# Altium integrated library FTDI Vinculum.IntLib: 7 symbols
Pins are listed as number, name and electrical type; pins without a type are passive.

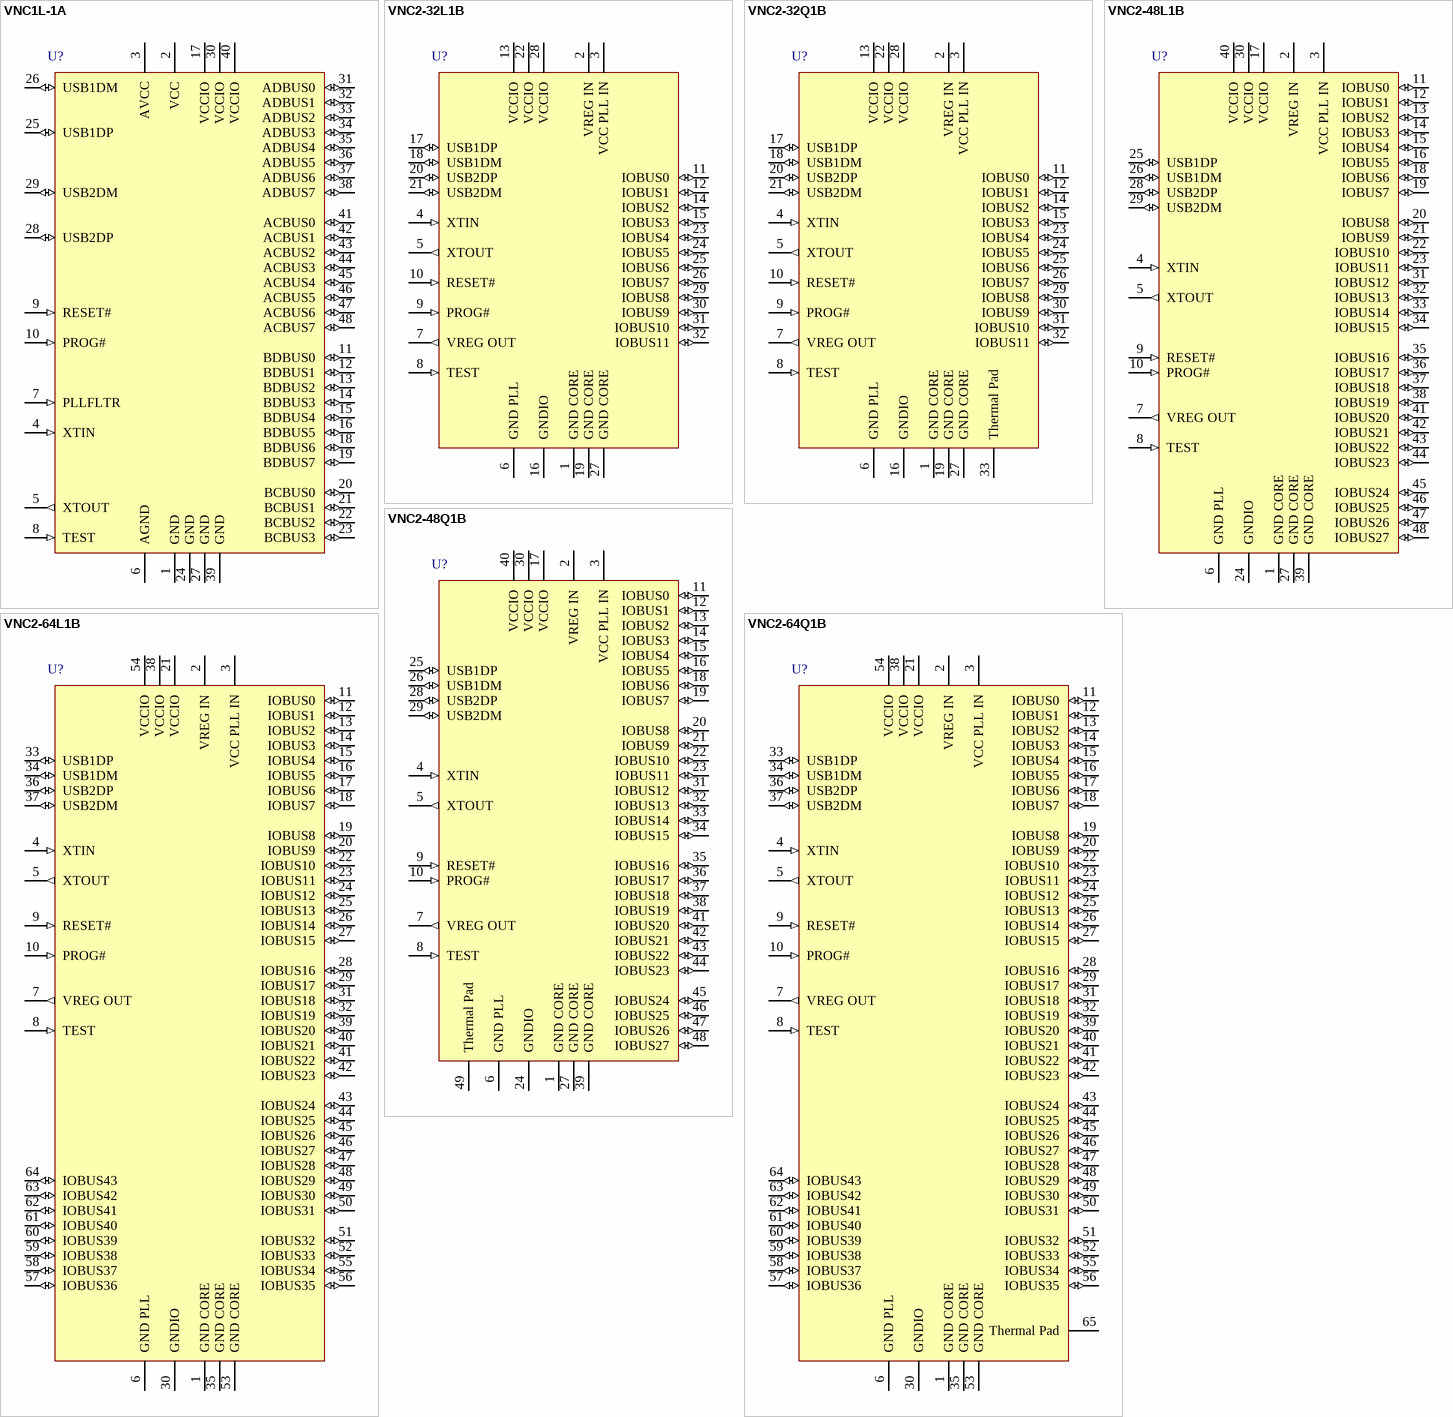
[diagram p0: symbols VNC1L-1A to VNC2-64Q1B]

## VNC1L-1A
designator U?
Vinculum Embedded USB Host Controller Chip, 48-pin LQFP; Manufacturer: FTDI; PartNumber: VNC1L-1A
footprint LQFP-48_N (Thin QFP, 48-Leads, Body 7x7mm, Pitch 0.5mm, IPC Medium Density)
footprint LQFP-48_L (Thin QFP, 48-Leads, Body 7x7mm, Pitch 0.5mm, IPC High Density)
footprint LQFP-48_M (Thin QFP, 48-Leads, Body 7x7mm, Pitch 0.5mm, IPC Low Density)
pins: 1 GND (power), 2 VCC (power), 3 AVCC (power), 4 XTIN (in), 5 XTOUT (out), 6 AGND (power), 7 PLLFLTR (in), 8 TEST (in), 9 RESET# (in), 10 PROG# (in), 11 BDBUS0 (io), 12 BDBUS1 (io), 13 BDBUS2 (io), 14 BDBUS3 (io), 15 BDBUS4 (io), 16 BDBUS5 (io), 17 VCCIO (power), 18 BDBUS6 (io), 19 BDBUS7 (io), 20 BCBUS0 (io), 21 BCBUS1 (io), 22 BCBUS2 (io), 23 BCBUS3 (io), 24 GND (power), 25 USB1DP (io), 26 USB1DM (io), 27 GND (power), 28 USB2DP (io), 29 USB2DM (io), 30 VCCIO (power), 31 ADBUS0 (io), 32 ADBUS1 (io), 33 ADBUS2 (io), 34 ADBUS3 (io), 35 ADBUS4 (io), 36 ADBUS5 (io), 37 ADBUS6 (io), 38 ADBUS7 (io), 39 GND (power), 40 VCCIO (power), 41 ACBUS0 (io), 42 ACBUS1 (io), 43 ACBUS2 (io), 44 ACBUS3 (io), 45 ACBUS4 (io), 46 ACBUS5 (io), 47 ACBUS6 (io), 48 ACBUS7 (io)

## VNC2-32L1B
designator U?
Vinculum-II Embedded Dual USB Host Controller Chip, 32-pin LQFP; Manufacturer: FTDI; PartNumber: VNC2-32L1B
footprint LQFP-32_N (Thin QFP, 32-Leads, Body 7x7mm, Pitch 0.8mm, IPC Medium Density)
footprint LQFP-32_L (Thin QFP, 32-Leads, Body 7x7mm, Pitch 0.8mm, IPC High Density)
footprint LQFP-32_M (Thin QFP, 32-Leads, Body 7x7mm, Pitch 0.8mm, IPC Low Density)
pins: 1 GND CORE (power), 2 VREG IN (power), 3 VCC PLL IN (power), 4 XTIN (in), 5 XTOUT (out), 6 GND PLL (power), 7 VREG OUT (out), 8 TEST (in), 9 PROG# (in), 10 RESET# (in), 11 IOBUS0 (io), 12 IOBUS1 (io), 13 VCCIO (power), 14 IOBUS2 (io), 15 IOBUS3 (io), 16 GNDIO (power), 17 USB1DP (io), 18 USB1DM (io), 19 GND CORE (power), 20 USB2DP (io), 21 USB2DM (io), 22 VCCIO (power), 23 IOBUS4 (io), 24 IOBUS5 (io), 25 IOBUS6 (io), 26 IOBUS7 (io), 27 GND CORE (power), 28 VCCIO (power), 29 IOBUS8 (io), 30 IOBUS9 (io), 31 IOBUS10 (io), 32 IOBUS11 (io)

## VNC2-32Q1B
designator U?
Vinculum-II Embedded Dual USB Host Controller Chip, 32-pin QFN; Manufacturer: FTDI; PartNumber: VNC2-32Q1B
footprint QFN7X7-32_N (QFN, 32-Leads, Body 7x7mm, Pitch 0.65mm, Thermal Pad 4.8x4.8mm, IPC Medium Density)
footprint QFN7X7-32_L (QFN, 32-Leads, Body 7x7mm, Pitch 0.65mm, Thermal Pad 4.8x4.8mm, IPC High Density)
footprint QFN7X7-32_M (QFN, 32-Leads, Body 7x7mm, Pitch 0.65mm, Thermal Pad 4.8x4.8mm, IPC Low Density)
pins: 1 GND CORE (power), 2 VREG IN (power), 3 VCC PLL IN (power), 4 XTIN (in), 5 XTOUT (out), 6 GND PLL (power), 7 VREG OUT (out), 8 TEST (in), 9 PROG# (in), 10 RESET# (in), 11 IOBUS0 (io), 12 IOBUS1 (io), 13 VCCIO (power), 14 IOBUS2 (io), 15 IOBUS3 (io), 16 GNDIO (power), 17 USB1DP (io), 18 USB1DM (io), 19 GND CORE (power), 20 USB2DP (io), 21 USB2DM (io), 22 VCCIO (power), 23 IOBUS4 (io), 24 IOBUS5 (io), 25 IOBUS6 (io), 26 IOBUS7 (io), 27 GND CORE (power), 28 VCCIO (power), 29 IOBUS8 (io), 30 IOBUS9 (io), 31 IOBUS10 (io), 32 IOBUS11 (io), 33 Thermal Pad

## VNC2-48L1B
designator U?
Vinculum-II Embedded Dual USB Host Controller Chip, 48-pin LQFP; Manufacturer: FTDI; PartNumber: VNC2-48L1B
footprint LQFP-48_N (Thin QFP, 48-Leads, Body 7x7mm, Pitch 0.5mm, IPC Medium Density)
footprint LQFP-48_L (Thin QFP, 48-Leads, Body 7x7mm, Pitch 0.5mm, IPC High Density)
footprint LQFP-48_M (Thin QFP, 48-Leads, Body 7x7mm, Pitch 0.5mm, IPC Low Density)
pins: 1 GND CORE (power), 2 VREG IN (power), 3 VCC PLL IN (power), 4 XTIN (in), 5 XTOUT (out), 6 GND PLL (power), 7 VREG OUT (out), 8 TEST (in), 9 RESET# (in), 10 PROG# (in), 11 IOBUS0 (io), 12 IOBUS1 (io), 13 IOBUS2 (io), 14 IOBUS3 (io), 15 IOBUS4 (io), 16 IOBUS5 (io), 17 VCCIO (power), 18 IOBUS6 (io), 19 IOBUS7 (io), 20 IOBUS8 (io), 21 IOBUS9 (io), 22 IOBUS10 (io), 23 IOBUS11 (io), 24 GNDIO (power), 25 USB1DP (io), 26 USB1DM (io), 27 GND CORE (power), 28 USB2DP (io), 29 USB2DM (io), 30 VCCIO (power), 31 IOBUS12 (io), 32 IOBUS13 (io), 33 IOBUS14 (io), 34 IOBUS15 (io), 35 IOBUS16 (io), 36 IOBUS17 (io), 37 IOBUS18 (io), 38 IOBUS19 (io), 39 GND CORE (power), 40 VCCIO (power), 41 IOBUS20 (io), 42 IOBUS21 (io), 43 IOBUS22 (io), 44 IOBUS23 (io), 45 IOBUS24 (io), 46 IOBUS25 (io), 47 IOBUS26 (io), 48 IOBUS27 (io)

## VNC2-48Q1B
designator U?
Vinculum-II Embedded Dual USB Host Controller Chip, 48-pin QFN; Manufacturer: FTDI; PartNumber: VNC2-48Q1B
footprint QFN48_N (QFN, 48-Leads, Body 8x8mm, Pitch 0.5mm, Thermal Pad 6.3x6.3mm, IPC Medium Density)
footprint QFN48_L (QFN, 48-Leads, Body 8x8mm, Pitch 0.5mm, Thermal Pad 6.3x6.3mm, IPC High Density)
footprint QFN48_M (QFN, 48-Leads, Body 8x8mm, Pitch 0.5mm, Thermal Pad 6.3x6.3mm, IPC Low Density)
pins: 1 GND CORE (power), 2 VREG IN (power), 3 VCC PLL IN (power), 4 XTIN (in), 5 XTOUT (out), 6 GND PLL (power), 7 VREG OUT (out), 8 TEST (in), 9 RESET# (in), 10 PROG# (in), 11 IOBUS0 (io), 12 IOBUS1 (io), 13 IOBUS2 (io), 14 IOBUS3 (io), 15 IOBUS4 (io), 16 IOBUS5 (io), 17 VCCIO (power), 18 IOBUS6 (io), 19 IOBUS7 (io), 20 IOBUS8 (io), 21 IOBUS9 (io), 22 IOBUS10 (io), 23 IOBUS11 (io), 24 GNDIO (power), 25 USB1DP (io), 26 USB1DM (io), 27 GND CORE (power), 28 USB2DP (io), 29 USB2DM (io), 30 VCCIO (power), 31 IOBUS12 (io), 32 IOBUS13 (io), 33 IOBUS14 (io), 34 IOBUS15 (io), 35 IOBUS16 (io), 36 IOBUS17 (io), 37 IOBUS18 (io), 38 IOBUS19 (io), 39 GND CORE (power), 40 VCCIO (power), 41 IOBUS20 (io), 42 IOBUS21 (io), 43 IOBUS22 (io), 44 IOBUS23 (io), 45 IOBUS24 (io), 46 IOBUS25 (io), 47 IOBUS26 (io), 48 IOBUS27 (io), 49 Thermal Pad

## VNC2-64L1B
designator U?
Vinculum-II Embedded Dual USB Host Controller Chip, 64-pin LQFP; Manufacturer: FTDI; PartNumber: VNC2-64L1B
footprint LQFP-64_N (Thin QFP, 64-Leads, Body 10x10mm, Pitch 0.5mm, IPC Medium Density)
footprint LQFP-64_L (Thin QFP, 64-Leads, Body 10x10mm, Pitch 0.5mm, IPC High Density)
footprint LQFP-64_M (Thin QFP, 64-Leads, Body 10x10mm, Pitch 0.5mm, IPC Low Density)
pins: 1 GND CORE (power), 2 VREG IN (power), 3 VCC PLL IN (power), 4 XTIN (in), 5 XTOUT (out), 6 GND PLL (power), 7 VREG OUT (out), 8 TEST (in), 9 RESET# (in), 10 PROG# (in), 11 IOBUS0 (io), 12 IOBUS1 (io), 13 IOBUS2 (io), 14 IOBUS3 (io), 15 IOBUS4 (io), 16 IOBUS5 (io), 17 IOBUS6 (io), 18 IOBUS7 (io), 19 IOBUS8 (io), 20 IOBUS9 (io), 21 VCCIO (power), 22 IOBUS10 (io), 23 IOBUS11 (io), 24 IOBUS12 (io), 25 IOBUS13 (io), 26 IOBUS14 (io), 27 IOBUS15 (io), 28 IOBUS16 (io), 29 IOBUS17 (io), 30 GNDIO (power), 31 IOBUS18 (io), 32 IOBUS19 (io), 33 USB1DP (io), 34 USB1DM (io), 35 GND CORE (power), 36 USB2DP (io), 37 USB2DM (io), 38 VCCIO (power), 39 IOBUS20 (io), 40 IOBUS21 (io), 41 IOBUS22 (io), 42 IOBUS23 (io), 43 IOBUS24 (io), 44 IOBUS25 (io), 45 IOBUS26 (io), 46 IOBUS27 (io), 47 IOBUS28 (io), 48 IOBUS29 (io), 49 IOBUS30 (io), 50 IOBUS31 (io), 51 IOBUS32 (io), 52 IOBUS33 (io), 53 GND CORE (power), 54 VCCIO (power), 55 IOBUS34 (io), 56 IOBUS35 (io), 57 IOBUS36 (io), 58 IOBUS37 (io), 59 IOBUS38 (io), 60 IOBUS39 (io), 61 IOBUS40 (io), 62 IOBUS41 (io), 63 IOBUS42 (io), 64 IOBUS43 (io)

## VNC2-64Q1B
designator U?
Vinculum-II Embedded Dual USB Host Controller Chip, 64-pin QFN; Manufacturer: FTDI; PartNumber: VNC2-64Q1B
footprint QFN64_N (QFN, 64-Leads, Body 8x8mm, Pitch 0.4mm, Thermal Pad 6.3x6.3mm, IPC Medium Density)
footprint QFN64_L (QFN, 64-Leads, Body 8x8mm, Pitch 0.4mm, Thermal Pad 6.3x6.3mm, IPC High Density)
footprint QFN64_M (QFN, 64-Leads, Body 8x8mm, Pitch 0.4mm, Thermal Pad 6.3x6.3mm, IPC Low Density)
pins: 1 GND CORE (power), 2 VREG IN (power), 3 VCC PLL IN (power), 4 XTIN (in), 5 XTOUT (out), 6 GND PLL (power), 7 VREG OUT (out), 8 TEST (in), 9 RESET# (in), 10 PROG# (in), 11 IOBUS0 (io), 12 IOBUS1 (io), 13 IOBUS2 (io), 14 IOBUS3 (io), 15 IOBUS4 (io), 16 IOBUS5 (io), 17 IOBUS6 (io), 18 IOBUS7 (io), 19 IOBUS8 (io), 20 IOBUS9 (io), 21 VCCIO (power), 22 IOBUS10 (io), 23 IOBUS11 (io), 24 IOBUS12 (io), 25 IOBUS13 (io), 26 IOBUS14 (io), 27 IOBUS15 (io), 28 IOBUS16 (io), 29 IOBUS17 (io), 30 GNDIO (power), 31 IOBUS18 (io), 32 IOBUS19 (io), 33 USB1DP (io), 34 USB1DM (io), 35 GND CORE (power), 36 USB2DP (io), 37 USB2DM (io), 38 VCCIO (power), 39 IOBUS20 (io), 40 IOBUS21 (io), 41 IOBUS22 (io), 42 IOBUS23 (io), 43 IOBUS24 (io), 44 IOBUS25 (io), 45 IOBUS26 (io), 46 IOBUS27 (io), 47 IOBUS28 (io), 48 IOBUS29 (io), 49 IOBUS30 (io), 50 IOBUS31 (io), 51 IOBUS32 (io), 52 IOBUS33 (io), 53 GND CORE (power), 54 VCCIO (power), 55 IOBUS34 (io), 56 IOBUS35 (io), 57 IOBUS36 (io), 58 IOBUS37 (io), 59 IOBUS38 (io), 60 IOBUS39 (io), 61 IOBUS40 (io), 62 IOBUS41 (io), 63 IOBUS42 (io), 64 IOBUS43 (io), 65 Thermal Pad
